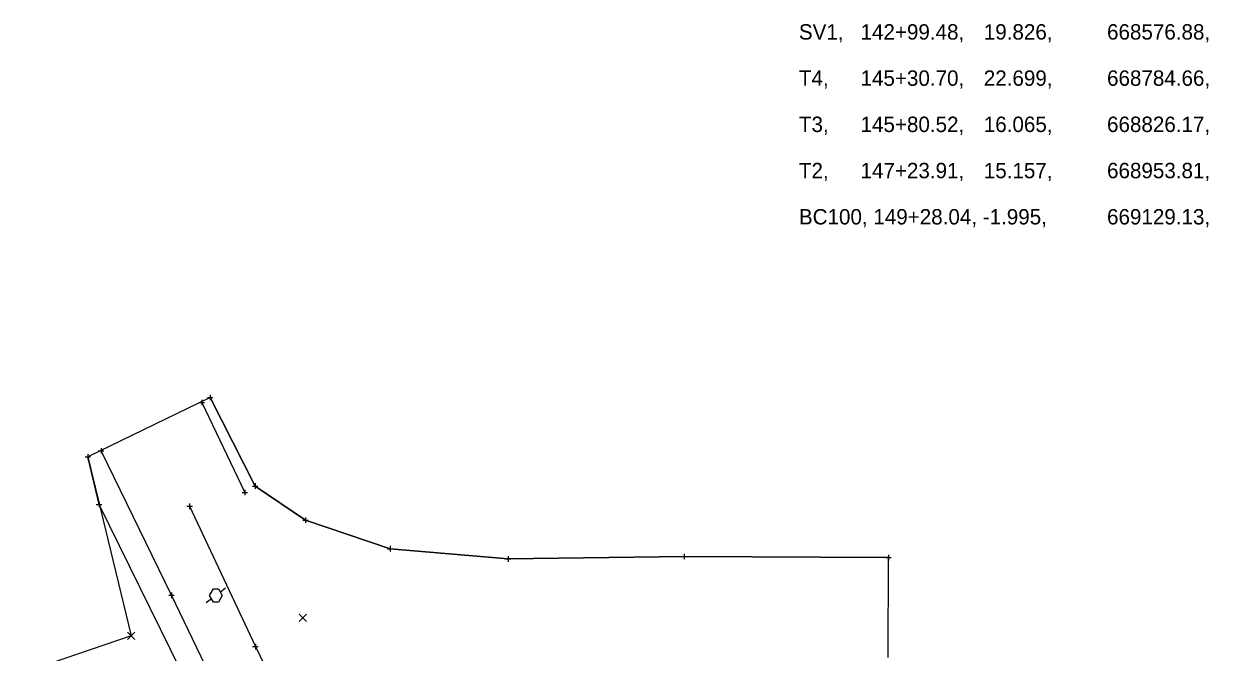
# Model space of a CAD drawing. Extents: x 1358778 to 1361523, y 667968 to 670334.
# Drawn here: x 1359593.6 to 1359811, y 669118.9 to 669233 of the extents above; entities that cross this region are included whole.
import ezdxf

# ---------------------------------------------------------------- set-up
doc = ezdxf.new("R2010")
doc.units = 0
for name, color, linetype in [('_CIVIL_CONSTRUCTION', 7, 'Continuous'), ('Default', 7, 'Continuous'), ('DV_X_Section_VMS_Line', 7, 'Continuous'), ('DV_X_State_Line', 7, 'Continuous'), ('PV_X_Shoulder_Aggregate', 7, 'Continuous'), ('RW_X_CL', 7, 'Continuous'), ('RW_X_Fee_RW', 7, 'Continuous'), ('SV_X_Terrain_Boundary', 7, 'Continuous')]:
    doc.layers.add(name, color=color, linetype=linetype)

msp = doc.modelspace()

# ---------------------------------------------------------------- linework, layer by layer
at = {"layer": '_CIVIL_CONSTRUCTION'}
for p, q in [((1359627.44, 669165.63), (1359627.44, 669164.63)), ((1359625.4, 669164.22), (1359626.4, 669164.22)), ((1359625.9, 669164.72), (1359625.9, 669163.72)), ((1359625.9, 669164.22), (1359625.9, 669164.22)), ((1359626.94, 669165.13), (1359627.94, 669165.13)), ((1359627.44, 669165.13), (1359627.44, 669165.13)), ((1359605.22, 669154.83), (1359605.22, 669153.83)), ((1359607.11, 669155.44), (1359608.11, 669155.44)), ((1359607.61, 669155.94), (1359607.61, 669154.94)), ((1359607.61, 669155.44), (1359607.61, 669155.44)), ((1359604.72, 669154.33), (1359605.72, 669154.33)), ((1359605.22, 669154.33), (1359605.22, 669154.33)), ((1359633.74, 669148.37), (1359633.74, 669147.37)), ((1359635.13, 669149.03), (1359636.13, 669149.03)), ((1359635.63, 669149.53), (1359635.63, 669148.53)), ((1359635.63, 669149.03), (1359635.63, 669149.03)), ((1359607.24, 669146.19), (1359607.24, 669145.19)), ((1359623.71, 669145.85), (1359623.71, 669144.85)), ((1359633.24, 669147.87), (1359634.24, 669147.87)), ((1359633.74, 669147.87), (1359633.74, 669147.87)), ((1359606.74, 669145.69), (1359607.74, 669145.69)), ((1359607.24, 669145.69), (1359607.24, 669145.69)), ((1359623.21, 669145.35), (1359624.21, 669145.35)), ((1359623.71, 669145.35), (1359623.71, 669145.35)), ((1359644.25, 669142.83), (1359645.25, 669142.83)), ((1359644.75, 669143.33), (1359644.75, 669142.33)), ((1359644.75, 669142.83), (1359644.75, 669142.83)), ((1359659.65, 669137.64), (1359660.65, 669137.64)), ((1359660.15, 669138.14), (1359660.15, 669137.14)), ((1359660.15, 669137.64), (1359660.15, 669137.64)), ((1359681.1, 669135.78), (1359682.1, 669135.78)), ((1359681.6, 669136.28), (1359681.6, 669135.28)), ((1359681.6, 669135.78), (1359681.6, 669135.78)), ((1359713.06, 669136.22), (1359714.06, 669136.22)), ((1359713.56, 669136.72), (1359713.56, 669135.72)), ((1359713.56, 669136.22), (1359713.56, 669136.22)), ((1359750.21, 669136.03), (1359751.21, 669136.03)), ((1359750.71, 669136.53), (1359750.71, 669135.53)), ((1359750.71, 669136.03), (1359750.71, 669136.03)), ((1359619.92, 669129.18), (1359620.92, 669129.18)), ((1359620.42, 669129.68), (1359620.42, 669128.68)), ((1359620.42, 669129.18), (1359620.42, 669129.18)), ((1359635.15, 669119.85), (1359636.15, 669119.85)), ((1359635.65, 669120.35), (1359635.65, 669119.35)), ((1359635.65, 669119.85), (1359635.65, 669119.85))]:
    msp.add_line(p, q, dxfattribs=at)
at = {"layer": 'DV_X_Section_VMS_Line'}
for points in [[(1359625.9, 669164.22), (1359633.74, 669147.87)], [(1359772.31, 668821.91), (1359760.1, 668845.87), (1359747.72, 668870.87), (1359734.52, 668897.17), (1359722.14, 668922.06), (1359709.17, 668947.81), (1359696.58, 668973.46), (1359683.8, 668999.2), (1359670.85, 669025.83), (1359658.37, 669051.06), (1359645.66, 669077.07), (1359633.44, 669102.12), (1359620.42, 669129.18), (1359607.61, 669155.44)]]:
    msp.add_lwpolyline(points, dxfattribs=at)
at = {"layer": 'DV_X_State_Line'}
for p, q in [((1359643.63, 669124.4), (1359644.96, 669125.73)), ((1359643.63, 669125.73), (1359644.96, 669124.4)), ((1359612.42, 669121.13), (1359613.76, 669122.47)), ((1359612.42, 669122.47), (1359613.76, 669121.13))]:
    msp.add_line(p, q, dxfattribs=at)
at = {"layer": 'PV_X_Shoulder_Aggregate'}
for points in [[(1359627.44, 669165.13), (1359635.63, 669149.03), (1359644.75, 669142.83), (1359660.15, 669137.64), (1359681.6, 669135.78), (1359713.56, 669136.22), (1359750.71, 669136.03)], [(1359769.47, 668822.02), (1359757.98, 668844.5), (1359745.41, 668870.31), (1359732.81, 668896.18), (1359720.6, 668921.26), (1359707.56, 668947.09), (1359694.79, 668972.7), (1359682.02, 668998.15), (1359674.4, 669011.37), (1359667.71, 669024.65), (1359655.8, 669049.55), (1359642.8, 669076.08), (1359631.19, 669100.74), (1359624.27, 669114.49), (1359622.09, 669115.51), (1359607.24, 669145.69), (1359605.22, 669154.33)]]:
    msp.add_lwpolyline(points, dxfattribs=at)
at = {"layer": 'RW_X_CL'}
msp.add_lwpolyline([(1359623.71, 669145.35), (1359635.65, 669119.85), (1359647.83, 669094.53), (1359660.13, 669069.76), (1359672.53, 669044.94), (1359684.89, 669019.59), (1359697.19, 668995.03), (1359709.88, 668969.31), (1359722.05, 668944.82), (1359734.23, 668920.57), (1359746.33, 668896.21), (1359758.41, 668872.25), (1359770.5, 668848.23), (1359783.68, 668821.67), (1359835.74, 668718.74), (1359848.17, 668694.11), (1359860.38, 668670.21), (1359872.43, 668646.02), (1359884.78, 668621.79), (1359897.37, 668596.99), (1359910.12, 668571.73), (1359922.3, 668547.01), (1359934.37, 668523.7)], dxfattribs=at)
at = {"layer": 'RW_X_Fee_RW'}
for p, q in [((1359627.68, 669128.53), (1359626.72, 669127.82)), ((1359630.25, 669130.45), (1359629.29, 669129.73))]:
    msp.add_line(p, q, dxfattribs=at)
msp.add_lwpolyline([(1359628.03, 669130.33), (1359628.93, 669130.33), (1359629.64, 669129.13), (1359628.93, 669127.93), (1359628.03, 669127.93), (1359627.32, 669129.13)], close=True, dxfattribs=at)
at = {"layer": 'SV_X_Terrain_Boundary'}
msp.add_lwpolyline([(1359750.69, 669117.88), (1359750.71, 669136.03), (1359713.56, 669136.22), (1359681.6, 669135.78), (1359660.15, 669137.64), (1359644.75, 669142.83), (1359635.63, 669149.03), (1359627.44, 669165.13), (1359605.22, 669154.33), (1359613.09, 669121.8), (1359593.59, 669115.13)], dxfattribs=at)

# ---------------------------------------------------------------- texts
at = {"layer": 'Default'}
for s, p in [('SV1,', (1359734.44, 669230.17)), ('142+99.48,', (1359745.64, 669230.17)), ('19.826,', (1359768.04, 669230.17)), ('668576.88,', (1359790.44, 669230.17)), ('T4,', (1359734.44, 669221.77)), ('145+30.70,', (1359745.64, 669221.77)), ('22.699,', (1359768.04, 669221.77)), ('668784.66,', (1359790.44, 669221.77)), ('T3,', (1359734.44, 669213.37)), ('145+80.52,', (1359745.64, 669213.37)), ('16.065,', (1359768.04, 669213.37)), ('668826.17,', (1359790.44, 669213.37)), ('T2,', (1359734.44, 669204.97)), ('147+23.91,', (1359745.64, 669204.97)), ('15.157,', (1359768.04, 669204.97)), ('668953.81,', (1359790.44, 669204.97)), ('BC100, 149+28.04, -1.995,', (1359734.44, 669196.57)), ('669129.13,', (1359790.44, 669196.57))]:
    msp.add_text(s, height=2.8, dxfattribs=at).set_placement(p)

doc.saveas('drawing.dxf')
